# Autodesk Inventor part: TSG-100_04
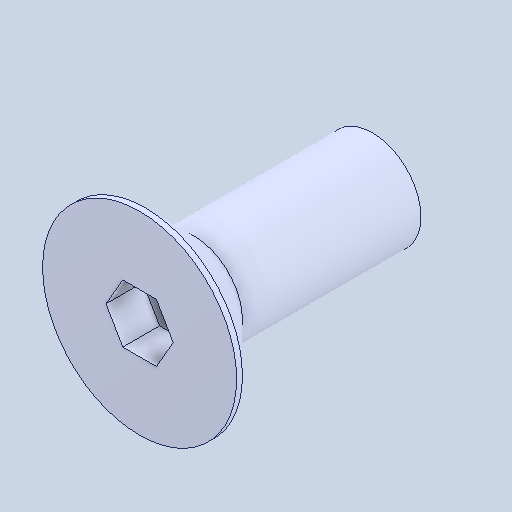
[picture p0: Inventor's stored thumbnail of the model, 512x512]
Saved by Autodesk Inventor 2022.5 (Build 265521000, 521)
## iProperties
Created: 2024-05
Part Number: TSG-100_04
Material: 一般
Document SubType Name: Modeling
Designer: ImaoCorp
Density: 1 g/cm^3
Appearance: 既定
Author: ImaoCorp
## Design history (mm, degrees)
feature "TSG-100_04"
node "ソリッド1"
